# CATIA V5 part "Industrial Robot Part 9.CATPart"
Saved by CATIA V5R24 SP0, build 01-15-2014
Part number: Industrial Robot Part 9
Source: Unknown
Material "Crisp Orange": density 7860 kg/m3, Young's modulus 2e+11 Pa, Poisson ratio 0.266
Bounding box of the stored display mesh (mm): x 1817.669 to 2061.104, y -144.125 to -55.998, z 1485.115 to 1595.115
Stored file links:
  C:\Users\cdl\Downloads\2024_CAD_final\p2\Industrial Robot Part 9.CATPart
  D:\Program Files\Dassault Systemes\B24\win_b64\startup\materials\Catalog.CATMaterial
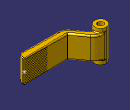
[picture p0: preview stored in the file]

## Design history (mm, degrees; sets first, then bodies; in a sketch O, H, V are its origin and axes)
Set1 "Reference Datas"
  Extract1: ExtractElem face of Solid1
  Point1: type OnCurve, Support edge of Extract1, Ratio 0.5
  Point2: type OnPlane, Support face of Solid1, RefPoint Point1, H 0, V 0, Direction (-1, 0, 0)
Body1 (main body), material "Crisp Orange"
  Solid1 "Solid 1": solid without history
